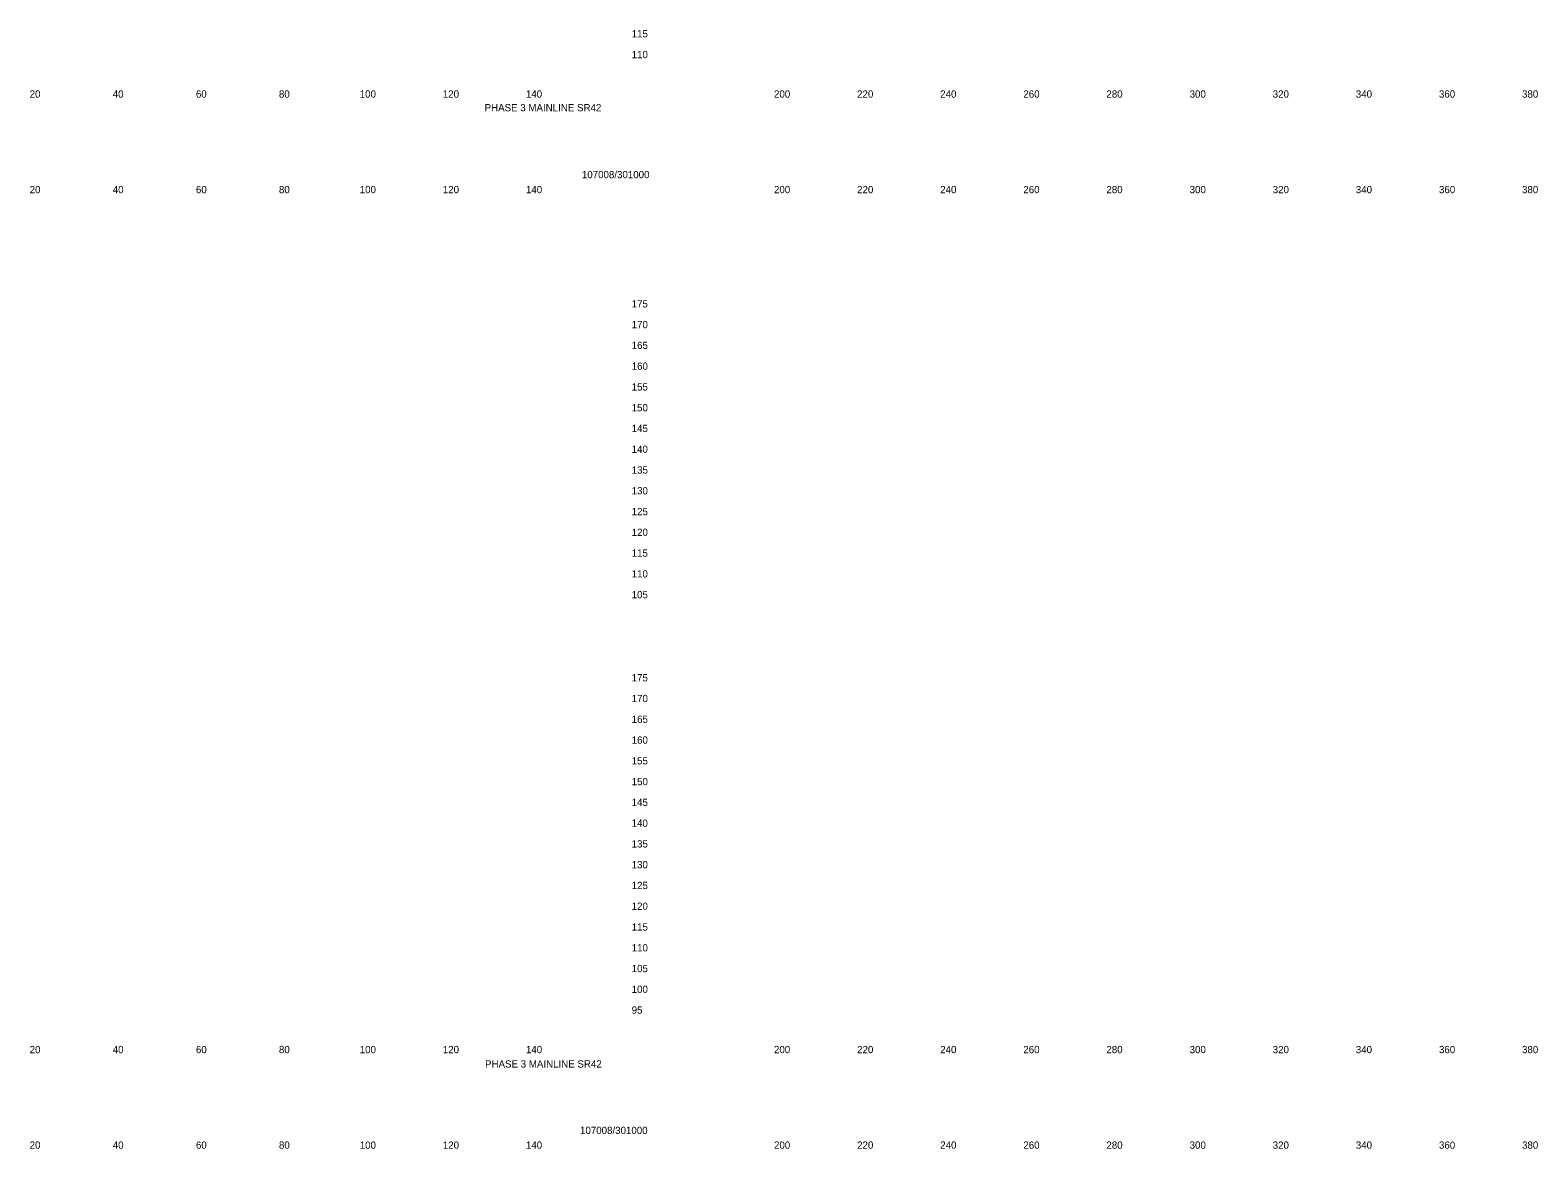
# Model space of a CAD drawing. Extents: x 21281 to 22024, y 6472 to 15198.
# Drawn here: x 21661.4 to 22024.2, y 12202.3 to 12471.6 of the extents above; entities that cross this region are included whole.
import ezdxf

# ---------------------------------------------------------------- set-up
doc = ezdxf.new("R2010")
doc.units = 0
doc.layers.add('Draft_XS_Grid', color=7, linetype='Continuous')
doc.layers.add('Draft_XS_Text', color=7, linetype='Continuous')

msp = doc.modelspace()

# ---------------------------------------------------------------- texts
at = {"layer": 'Draft_XS_Grid'}
for s, p in [('  115  ', (21804.84, 12469.84)), ('  110  ', (21804.84, 12464.84)), ('  175  ', (21804.84, 12404.84)), ('  170  ', (21804.84, 12399.84)), ('  165  ', (21804.84, 12394.84)), ('  160  ', (21804.84, 12389.84)), ('  155  ', (21804.84, 12384.84)), ('  150  ', (21804.84, 12379.84)), ('  145  ', (21804.84, 12374.84)), ('  140  ', (21804.84, 12369.84)), ('  135  ', (21804.84, 12364.84)), ('  130  ', (21804.84, 12359.84)), ('  125  ', (21804.84, 12354.84)), ('  120  ', (21804.84, 12349.84)), ('  115  ', (21804.84, 12344.84)), ('  110  ', (21804.84, 12339.84)), ('  105  ', (21804.84, 12334.84)), ('  175  ', (21804.84, 12314.84)), ('  170  ', (21804.84, 12309.84)), ('  165  ', (21804.84, 12304.84)), ('  160  ', (21804.84, 12299.84)), ('  155  ', (21804.84, 12294.84)), ('  150  ', (21804.84, 12289.84)), ('  145  ', (21804.84, 12284.84)), ('  140  ', (21804.84, 12279.84)), ('  135  ', (21804.84, 12274.84)), ('  130  ', (21804.84, 12269.84)), ('  125  ', (21804.84, 12264.84)), ('  120  ', (21804.84, 12259.84)), ('  115  ', (21804.84, 12254.84)), ('  110  ', (21804.84, 12249.84)), ('  105  ', (21804.84, 12244.84)), ('  100  ', (21804.84, 12239.84)), ('  95  ', (21804.84, 12234.84))]:
    msp.add_text(s, height=1.75, dxfattribs=at).set_placement(p)
at = {"layer": 'Draft_XS_Text'}
for s, p in [('  20  ', (21659.95, 12455.34)), ('  40  ', (21679.95, 12455.34)), ('  60  ', (21699.97, 12455.34)), ('  80  ', (21719.95, 12455.34)), ('  100  ', (21739.39, 12455.34)), ('  120  ', (21759.39, 12455.34)), ('PHASE 3 MAINLINE SR42', (21770.75, 12452.05)), ('  140  ', (21779.39, 12455.34)), ('  200  ', (21839.1, 12455.34)), ('  220  ', (21859.1, 12455.34)), ('  240  ', (21879.1, 12455.34)), ('  260  ', (21899.11, 12455.34)), ('  280  ', (21919.1, 12455.34)), ('  300  ', (21939.13, 12455.34)), ('  320  ', (21959.13, 12455.34)), ('  340  ', (21979.13, 12455.34)), ('  360  ', (21999.14, 12455.34)), ('  380  ', (22019.13, 12455.34)), ('107008/301000', (21794.16, 12435.95)), ('  20  ', (21659.95, 12432.34)), ('  40  ', (21679.95, 12432.34)), ('  60  ', (21699.97, 12432.34)), ('  80  ', (21719.95, 12432.34)), ('  100  ', (21739.39, 12432.34)), ('  120  ', (21759.39, 12432.34)), ('  140  ', (21779.39, 12432.34)), ('  200  ', (21839.1, 12432.34)), ('  220  ', (21859.1, 12432.34)), ('  240  ', (21879.1, 12432.34)), ('  260  ', (21899.11, 12432.34)), ('  280  ', (21919.1, 12432.34)), ('  300  ', (21939.13, 12432.34)), ('  320  ', (21959.13, 12432.34)), ('  340  ', (21979.13, 12432.34)), ('  360  ', (21999.14, 12432.34)), ('  380  ', (22019.13, 12432.34)), ('  20  ', (21659.95, 12225.34)), ('  40  ', (21679.95, 12225.34)), ('  60  ', (21699.97, 12225.34)), ('  80  ', (21719.95, 12225.34)), ('  100  ', (21739.39, 12225.34)), ('  120  ', (21759.39, 12225.34)), ('  140  ', (21779.39, 12225.34)), ('  200  ', (21839.1, 12225.34)), ('  220  ', (21859.1, 12225.34)), ('  240  ', (21879.1, 12225.34)), ('  260  ', (21899.11, 12225.34)), ('  280  ', (21919.1, 12225.34)), ('  300  ', (21939.13, 12225.34)), ('  320  ', (21959.13, 12225.34)), ('  340  ', (21979.13, 12225.34)), ('  360  ', (21999.14, 12225.34)), ('  380  ', (22019.13, 12225.34)), ('PHASE 3 MAINLINE SR42', (21770.85, 12221.87)), ('107008/301000', (21793.71, 12205.88)), ('  20  ', (21659.95, 12202.34)), ('  40  ', (21679.95, 12202.34)), ('  60  ', (21699.97, 12202.34)), ('  80  ', (21719.95, 12202.34)), ('  100  ', (21739.39, 12202.34)), ('  120  ', (21759.39, 12202.34)), ('  140  ', (21779.39, 12202.34)), ('  200  ', (21839.1, 12202.34)), ('  220  ', (21859.1, 12202.34)), ('  240  ', (21879.1, 12202.34)), ('  260  ', (21899.11, 12202.34)), ('  280  ', (21919.1, 12202.34)), ('  300  ', (21939.13, 12202.34)), ('  320  ', (21959.13, 12202.34)), ('  340  ', (21979.13, 12202.34)), ('  360  ', (21999.14, 12202.34)), ('  380  ', (22019.13, 12202.34))]:
    msp.add_text(s, height=1.75, dxfattribs=at).set_placement(p)

doc.saveas('drawing.dxf')
